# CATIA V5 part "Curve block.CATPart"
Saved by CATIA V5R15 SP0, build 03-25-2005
Part number: Curve block
Bounding box of the stored display mesh (mm): x -196.59 to 455, y -212.123 to 37.5, z -40 to 40
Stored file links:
  E:\#01 CATIA Lecture Materials\#06 DMU\#11 DMU Page01 KIN EX11\Curve block.CATPart
  C:\Documents and Settings\master\바탕 화면\Assem\승보\prodo(shaft1-1).CATPart
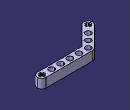
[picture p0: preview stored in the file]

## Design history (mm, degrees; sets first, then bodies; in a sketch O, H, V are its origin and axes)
Body1 (main body)
  Sketch1 on xy-plane, origin (0, 0, 0), H (1, 0, 0), V (0, 1, 0)
    line L1 (455, 37.5) -> (0, 37.5)
    point P2 (0, 37.5)
    line L2 (0, 37.5) -> (-212.132, -174.632)
    line L3 (-212.132, -174.632) -> (-159.099, -227.665)
    line L4 (-159.099, -227.665) -> (31.066, -37.5)
    line L5 (31.066, -37.5) -> (455, -37.5)
    line L6 (455, -37.5) -> (455, 37.5)
    distance L1 L5 = 75
    distance L4 L2 = 75
    distance V L6 = 455
    angle L4 L5 = 135
    length L2 = 300
    coincidence: P2 V
    horizontal: L1 H, L5 H
    perpendicularity: L3 L2
    vertical: L6 V
    symmetry: L1 L5 H
  Pad1: profile Sketch1, direction (0, 0, 1), length 40, mirrored extent
  Fillet1: radius 37.5, on edge [face of Pad1 from Sketch1.L6 | face of Pad1 from Sketch1.L5]; edge [face of Pad1 from Sketch1.L1 | face of Pad1 from Sketch1.L6]; edge [face of Pad1 from Sketch1.L4 | face of Pad1 from Sketch1.L3]; edge [face of Pad1 from Sketch1.L3 | face of Pad1 from Sketch1.L2]
  Sketch2 on end face of Pad1, origin (0, 0, 40), H (1, 0, 0), V (0, 1, 0)
    circle A1 centre (15.533, 0) radius 24.25
    point P1 (15.533, 0)
    circle A2 centre (94.533, 0) radius 24.25
    point P2 (94.533, 0)
    reference projected line E1 (455, 37.5) -> (0, 37.5) from edge [face of Pad1 from Sketch1.L1 | end face of Pad1]
    circle A3 centre (173.533, 0) radius 24.25
    point P3 (173.533, 0)
    circle A4 centre (252.533, 0) radius 24.25
    point P4 (252.533, 0)
    circle A5 centre (331.533, 0) radius 24.25
    point P5 (331.533, 0)
    circle A6 centre (-40.3284, -55.8614) radius 24.25
    point P6 (-40.3284, -55.8614)
    circle A7 centre (-96.1899, -111.7229) radius 24.25
    point P7 (-96.1899, -111.7229)
    reference projected line E2 (455, 37.5) -> (0, 37.5) from edge [face of Pad1 from Sketch1.L1 | end face of Pad1]
    reference projected line E3 (455, 37.5) -> (0, 37.5) from edge [face of Pad1 from Sketch1.L1 | end face of Pad1]
    construction line L1 (15.533, 0) -> (-124.9136, -140.4466)
    reference projected line E4 (-159.099, -227.665) -> (31.066, -37.5) from edge [face of Pad1 from Sketch1.L4 | end face of Pad1]
    axis line L2 (-34.3912, 120.5277) -> (68.2449, -127.2577)
    reference projected point E5 (31.066, -37.5) from vertex [face of Pad1 from Sketch1.L5 | end face of Pad1 | face of Pad1 from Sketch1.L4]
    reference projected point E6 (0, 37.5) from vertex [face of Pad1 from Sketch1.L2 | end face of Pad1 | face of Pad1 from Sketch1.L1]
    reference projected line E7 (455, 37.5) -> (0, 37.5) from edge [face of Pad1 from Sketch1.L1 | end face of Pad1]
    reference projected line E8 (31.066, -37.5) -> (455, -37.5) from edge [face of Pad1 from Sketch1.L5 | end face of Pad1]
    radius A2 = 24.25
    distance P2 E1 = 37.5
    radius A1 = 24.25
    radius A3 = 24.25
    radius A4 = 24.25
    radius A5 = 24.25
    distance P4 E2 = 37.5
    distance P5 E3 = 37.5
    distance P1 P2 = 79
    distance P2 P3 = 79
    distance P4 P3 = 79
    distance P4 P5 = 79
    radius A6 = 24.25
    radius A7 = 24.25
    distance P6 P1 = 79
    distance P7 P6 = 79
    coincidence: P3 H, P6 L1, P7 L1, L2 E5, L2 E6, P1 L2
    parallelism: L1 E4
    equidistance: E7 E8 P1
  Pocket1: profile Sketch2, direction (0, 0, -1), through (limit type 6)
  Fillet2: radius 30, on edge [face of Pad1 from Sketch1.L2 | face of Pad1 from Sketch1.L1]
  Sketch3 on end face of Pad1, origin (0, 0, 40), H (1, 0, 0), V (0, 1, 0)
    point P3 (415.53, 0)
    arc A1 centre (415.53, 0) radius 23.8 from (424.78, 21.9289) to (406.28, 21.9289) ccw
    line L1 (406.28, 9.25) -> (406.28, 21.9289)
    line L2 (393.6011, 9.25) -> (406.28, 9.25)
    arc A2 centre (415.53, 0) radius 23.8 from (393.6011, 9.25) to (393.6011, -9.25) ccw
    line L3 (406.28, -9.25) -> (393.6011, -9.25)
    line L4 (406.28, -21.9289) -> (406.28, -9.25)
    arc A3 centre (415.53, 0) radius 23.8 from (406.28, -21.9289) to (424.78, -21.9289) ccw
    line L5 (424.78, -9.25) -> (424.78, -21.9289)
    line L6 (437.4589, -9.25) -> (424.78, -9.25)
    arc A4 centre (415.53, 0) radius 23.8 from (437.4589, -9.25) to (437.4589, 9.25) ccw
    line L7 (424.78, 9.25) -> (437.4589, 9.25)
    line L8 (424.78, 21.9289) -> (424.78, 9.25)
    construction line L9 (354.2857, 0) -> (464.8589, 0)
    point P14 (354.2857, 0)
    construction line L10 (415.53, 51.6613) -> (415.53, -37.4321)
    line L11 (-168.349, -165.382) -> (-168.349, -152.7031)
    point P21 (-159.099, -174.632)
    arc A5 centre (-159.099, -174.632) radius 23.8 from (-149.849, -152.7031) to (-168.349, -152.7031) ccw
    line L12 (-149.849, -152.7031) -> (-149.849, -165.382)
    line L13 (-149.849, -165.382) -> (-137.1701, -165.382)
    arc A6 centre (-159.099, -174.632) radius 23.8 from (-137.1701, -183.882) to (-137.1701, -165.382) ccw
    line L14 (-137.1701, -183.882) -> (-149.849, -183.882)
    line L15 (-149.849, -183.882) -> (-149.849, -196.561)
    arc A7 centre (-159.099, -174.632) radius 23.8 from (-168.349, -196.561) to (-149.849, -196.561) ccw
    line L16 (-168.349, -196.561) -> (-168.349, -183.882)
    line L17 (-168.349, -183.882) -> (-181.0279, -183.882)
    arc A8 centre (-159.099, -174.632) radius 23.8 from (-181.0279, -165.382) to (-181.0279, -183.882) ccw
    line L18 (-181.0279, -165.382) -> (-168.349, -165.382)
    construction line L19 (-159.099, -174.632) -> (-113.8002, -129.3332)
    reference projected line E1 (-159.099, -227.665) -> (31.066, -37.5) from edge [face of Pad1 from Sketch1.L4 | end face of Pad1]
    reference projected line E2 (-159.099, -227.665) -> (31.066, -37.5) from edge [face of Pad1 from Sketch1.L4 | end face of Pad1]
    construction line L20 (-159.099, -131.1889) -> (-159.099, -239.7036)
    axis line L21 (-193.6767, -174.632) -> (-68.5447, -174.632)
    reference projected arc E3 centre (-159.099, -174.632) radius 37.5 from (-185.6155, -201.1485) to (-132.5825, -201.1485) ccw from edge [end face of Pad1 | face of Fillet1]
    distance P3 V = 415.53
    distance L1 L8 = 18.5
    distance L7 L6 = 18.5
    radius A4 = 23.8
    distance L5 L4 = 18.5
    distance L2 L3 = 18.5
    radius A3 = 23.8
    distance L19 E2 = 37.5
    radius A7 = 23.8
    distance L16 L15 = 18.5
    distance L14 L13 = 18.5
    distance L17 L18 = 18.5
    distance L11 L12 = 18.5
    radius A8 = 23.8
    distance L21 A7 = 23.8
    coincidence: P3 H, P14 H, L10 P3, L18 L13, L11 L16, A5 A6
    horizontal: L9 H, L21 H
    vertical: L10 V, L4 V, L20 V
    symmetry: A4 A2 L10, A1 A3 L9, L5 L4 L10, L3 L2 L9, L6 L7 L9, L8 L1 L10, L13 L14 L21, A8 A6 L20, L16 L15 L20
    parallelism: L19 E1
    concentricity: P21 E3
  Pocket2: profile Sketch3, direction (0, 0, -1), through (limit type 6)
  Fillet3: radius 3, on edge [face of Pocket2 from Sketch3.L2 | face of Pocket2 from Sketch3.L1]; edge [face of Pocket2 from Sketch3.L4 | face of Pocket2 from Sketch3.L3]; edge [face of Pocket2 from Sketch3.L8 | face of Pocket2 from Sketch3.L7]; edge [face of Pocket2 from Sketch3.L6 | face of Pocket2 from Sketch3.L5]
